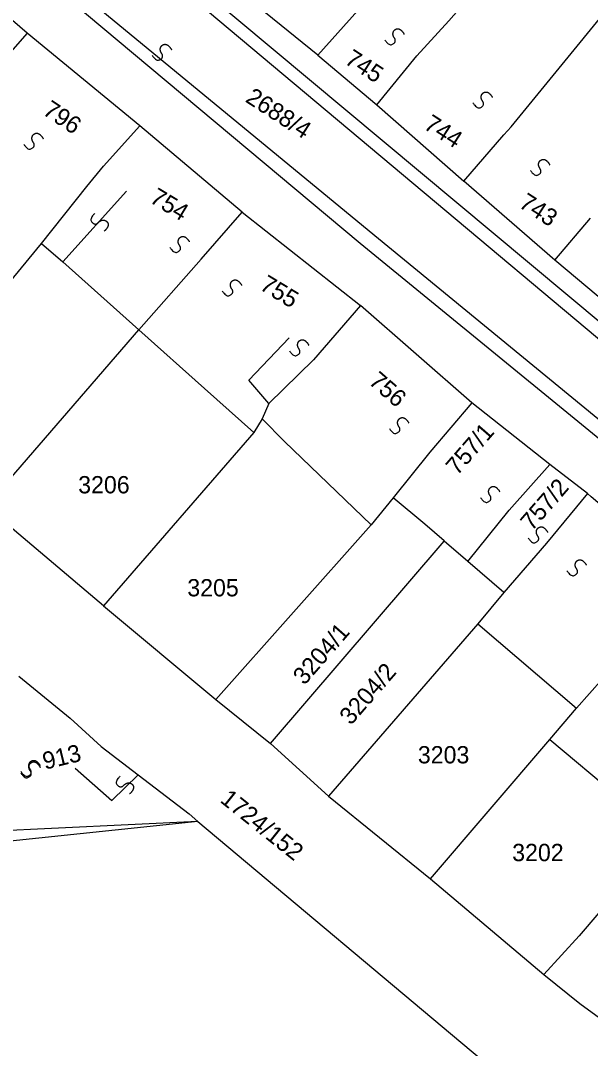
# Model space of a CAD drawing. Extents: x -581999 to -572728, y -1219553 to -1212032.
# Drawn here: x -578520.6 to -578454.7, y -1215566 to -1215447.1 of the extents above; entities that cross this region are included whole.
import ezdxf

# ---------------------------------------------------------------- set-up
doc = ezdxf.new("R2010")
doc.units = 0
for name, color, linetype in [('Vrstva 1', 7, 'Continuous'), ('Vrstva 2', 7, 'Continuous'), ('Vrstva 4', 7, 'Continuous'), ('Vrstva 6', 7, 'Continuous')]:
    doc.layers.add(name, color=color, linetype=linetype)

msp = doc.modelspace()

# ---------------------------------------------------------------- linework, layer by layer
at = {"layer": 'Vrstva 1'}
for p, q in [((-578477.551, -1215502.316), (-578480.099, -1215505.441)), ((-578480.099, -1215505.441), (-578498.028, -1215525.656)), ((-578500.138, -1215539.76), (-578537.866, -1215543.74)), ((-578500.138, -1215539.76), (-578467.315, -1215567.303))]:
    msp.add_line(p, q, dxfattribs=at)
for points in [[(-578471.09, -1215447.169), (-578456.35, -1215430.437)], [(-578519.857, -1215448.603), (-578526.636, -1215442.735), (-578533.826, -1215437.135)], [(-578463.903, -1215459.404), (-578447.102, -1215438.847)], [(-578504.23, -1215439.686), (-578419.077, -1215510.839)], [(-578518.647, -1215441.616), (-578481.363, -1215472.872)], [(-578486.244, -1215451.147), (-578495.73, -1215443.433)], [(-578481.605, -1215445.983), (-578486.244, -1215451.147)], [(-578474.801, -1215451.197), (-578471.09, -1215447.169)], [(-578519.857, -1215448.603), (-578524.032, -1215453.273)], [(-578506.841, -1215459.305), (-578519.857, -1215448.603)], [(-578486.244, -1215451.147), (-578479.439, -1215456.879)], [(-578479.439, -1215456.879), (-578474.801, -1215451.197)], [(-578479.439, -1215456.879), (-578469.365, -1215465.703)], [(-578511.015, -1215463.974), (-578506.841, -1215459.305)], [(-578494.997, -1215469.285), (-578506.841, -1215459.305)], [(-578464.727, -1215460.333), (-578463.903, -1215459.404)], [(-578469.365, -1215465.703), (-578464.727, -1215460.333)], [(-578512.957, -1215466.31), (-578511.015, -1215463.974)], [(-578458.834, -1215474.839), (-578469.365, -1215465.703)], [(-578518.199, -1215472.928), (-578512.957, -1215466.31)], [(-578499.753, -1215474.733), (-578494.997, -1215469.285)], [(-578494.997, -1215469.285), (-578481.325, -1215480.074)], [(-578458.834, -1215474.839), (-578454.712, -1215469.985)], [(-578522.277, -1215477.891), (-578518.199, -1215472.928)], [(-578518.199, -1215472.928), (-578515.719, -1215475.014)], [(-578481.363, -1215472.872), (-578433.992, -1215511.611)], [(-578515.719, -1215475.014), (-578506.936, -1215482.904)], [(-578506.936, -1215482.904), (-578499.753, -1215474.733)], [(-578446.669, -1215485.073), (-578458.834, -1215474.839)], [(-578481.325, -1215480.074), (-578486.751, -1215486.386)], [(-578468.429, -1215491.325), (-578481.325, -1215480.074)], [(-578524.621, -1215503.324), (-578506.936, -1215482.904)], [(-578506.936, -1215482.904), (-578499.341, -1215489.68)], [(-578486.751, -1215486.386), (-578491.903, -1215491.423)], [(-578499.341, -1215489.68), (-578493.633, -1215494.772)], [(-578491.903, -1215491.423), (-578492.681, -1215493.205)], [(-578468.429, -1215491.325), (-578473.281, -1215497.063)], [(-578459.402, -1215498.487), (-578468.429, -1215491.325)], [(-578492.681, -1215493.205), (-578493.633, -1215494.772)], [(-578492.681, -1215493.205), (-578490.117, -1215495.804)], [(-578493.633, -1215494.772), (-578511.025, -1215514.8)], [(-578490.117, -1215495.804), (-578480.099, -1215505.441)], [(-578473.281, -1215497.063), (-578477.551, -1215502.316)], [(-578464.134, -1215503.758), (-578459.402, -1215498.487)], [(-578455.068, -1215501.843), (-578459.402, -1215498.487)], [(-578473.862, -1215505.357), (-578477.551, -1215502.316)], [(-578455.068, -1215501.843), (-578459.8, -1215507.554)], [(-578443.423, -1215511.787), (-578454.656, -1215502.207), (-578455.045, -1215501.815), (-578455.068, -1215501.843)], [(-578511.025, -1215514.8), (-578524.621, -1215503.324)], [(-578468.913, -1215509.672), (-578464.134, -1215503.758)], [(-578471.624, -1215507.325), (-578471.63, -1215507.318), (-578473.862, -1215505.357)], [(-578491.718, -1215530.756), (-578471.624, -1215507.325)], [(-578468.913, -1215509.672), (-578471.624, -1215507.325)], [(-578459.8, -1215507.554), (-578464.749, -1215513.291)], [(-578464.749, -1215513.291), (-578468.913, -1215509.672)], [(-578464.749, -1215513.291), (-578467.757, -1215516.889)], [(-578511.025, -1215514.8), (-578498.028, -1215525.656)], [(-578467.757, -1215516.889), (-578485.029, -1215536.824)], [(-578467.757, -1215516.889), (-578456.328, -1215526.663)], [(-578520.831, -1215522.95), (-578514.896, -1215527.797)], [(-578456.328, -1215526.663), (-578453.319, -1215523.26)], [(-578498.028, -1215525.656), (-578491.718, -1215530.756)], [(-578459.432, -1215530.26), (-578456.328, -1215526.663)], [(-578514.896, -1215527.797), (-578511.286, -1215531.103), (-578507.032, -1215534.367)], [(-578491.718, -1215530.756), (-578485.029, -1215536.824)], [(-578473.211, -1215546.401), (-578459.432, -1215530.26)], [(-578459.432, -1215530.26), (-578451.583, -1215536.838)], [(-578507.032, -1215534.367), (-578501.109, -1215538.878), (-578500.138, -1215539.76), (-578532.369, -1215541.293)], [(-578485.029, -1215536.824), (-578473.211, -1215546.401)], [(-578446.238, -1215541.531), (-578456.037, -1215553.003)], [(-578473.211, -1215546.401), (-578460.112, -1215557.474)], [(-578456.037, -1215553.003), (-578460.112, -1215557.474)], [(-578460.112, -1215557.474), (-578455.94, -1215560.806)], [(-578455.94, -1215560.806), (-578449.558, -1215565.489)]]:
    msp.add_lwpolyline(points, dxfattribs=at)
at = {"layer": 'Vrstva 4'}
for p, q in [((-578514.298, -1215533.592), (-578510.056, -1215537.321)), ((-578510.056, -1215537.321), (-578507.032, -1215534.367))]:
    msp.add_line(p, q, dxfattribs=at)
for points in [[(-578505.224, -1215440.747), (-578421.464, -1215511.032)], [(-578516.36, -1215441.712), (-578479.233, -1215472.341)], [(-578515.719, -1215475.014), (-578508.358, -1215466.857)], [(-578479.233, -1215472.341), (-578312.417, -1215609.28)], [(-578489.562, -1215483.807), (-578494.245, -1215488.722)], [(-578491.903, -1215491.423), (-578494.245, -1215488.722)]]:
    msp.add_lwpolyline(points, dxfattribs=at)
at = {"layer": 'Vrstva 6'}
for points in [[(-578478.511, -1215449.348), (-578478.031, -1215450.055), (-578477.337, -1215449.744), (-578477.26, -1215449.344), (-578477.496, -1215448.999), (-578477.581, -1215448.667), (-578477.499, -1215448.377), (-578477.355, -1215448.197), (-578477.119, -1215448.069), (-578476.754, -1215448.105), (-578476.327, -1215448.544), (-578476.272, -1215448.717)], [(-578505.42, -1215451.141), (-578504.94, -1215451.848), (-578504.246, -1215451.537), (-578504.169, -1215451.137), (-578504.405, -1215450.792), (-578504.49, -1215450.46), (-578504.408, -1215450.17), (-578504.264, -1215449.99), (-578504.028, -1215449.862), (-578503.663, -1215449.898), (-578503.236, -1215450.337), (-578503.181, -1215450.51)], [(-578468.311, -1215456.656), (-578467.831, -1215457.363), (-578467.137, -1215457.052), (-578467.06, -1215456.652), (-578467.296, -1215456.307), (-578467.381, -1215455.975), (-578467.299, -1215455.685), (-578467.155, -1215455.505), (-578466.919, -1215455.377), (-578466.554, -1215455.413), (-578466.127, -1215455.852), (-578466.072, -1215456.025)], [(-578520.263, -1215461.424), (-578519.783, -1215462.131), (-578519.089, -1215461.82), (-578519.012, -1215461.42), (-578519.248, -1215461.075), (-578519.333, -1215460.743), (-578519.251, -1215460.453), (-578519.107, -1215460.273), (-578518.871, -1215460.145), (-578518.506, -1215460.181), (-578518.079, -1215460.62), (-578518.024, -1215460.793)], [(-578461.672, -1215464.451), (-578461.192, -1215465.158), (-578460.498, -1215464.847), (-578460.421, -1215464.447), (-578460.657, -1215464.102), (-578460.742, -1215463.77), (-578460.66, -1215463.48), (-578460.516, -1215463.3), (-578460.28, -1215463.172), (-578459.915, -1215463.208), (-578459.488, -1215463.647), (-578459.433, -1215463.82)], [(-578512.068, -1215469.441), (-578512.655, -1215470.063), (-578512.2, -1215470.672), (-578511.794, -1215470.66), (-578511.508, -1215470.355), (-578511.202, -1215470.201), (-578510.902, -1215470.217), (-578510.695, -1215470.319), (-578510.519, -1215470.522), (-578510.474, -1215470.886), (-578510.809, -1215471.398), (-578510.967, -1215471.49)], [(-578503.348, -1215473.369), (-578502.868, -1215474.076), (-578502.174, -1215473.765), (-578502.097, -1215473.365), (-578502.333, -1215473.02), (-578502.418, -1215472.688), (-578502.336, -1215472.398), (-578502.192, -1215472.218), (-578501.956, -1215472.09), (-578501.591, -1215472.126), (-578501.164, -1215472.565), (-578501.109, -1215472.738)], [(-578497.307, -1215478.389), (-578496.827, -1215479.096), (-578496.133, -1215478.785), (-578496.056, -1215478.385), (-578496.292, -1215478.04), (-578496.377, -1215477.708), (-578496.295, -1215477.418), (-578496.151, -1215477.238), (-578495.915, -1215477.11), (-578495.55, -1215477.146), (-578495.123, -1215477.585), (-578495.068, -1215477.758)], [(-578489.541, -1215485.313), (-578489.061, -1215486.02), (-578488.367, -1215485.709), (-578488.29, -1215485.309), (-578488.526, -1215484.964), (-578488.611, -1215484.632), (-578488.529, -1215484.342), (-578488.385, -1215484.162), (-578488.149, -1215484.034), (-578487.784, -1215484.07), (-578487.357, -1215484.509), (-578487.302, -1215484.682)], [(-578477.977, -1215494.315), (-578477.497, -1215495.022), (-578476.803, -1215494.711), (-578476.726, -1215494.311), (-578476.962, -1215493.966), (-578477.047, -1215493.634), (-578476.965, -1215493.344), (-578476.821, -1215493.164), (-578476.585, -1215493.036), (-578476.22, -1215493.072), (-578475.793, -1215493.511), (-578475.738, -1215493.684)], [(-578467.449, -1215502.278), (-578466.969, -1215502.985), (-578466.275, -1215502.674), (-578466.198, -1215502.274), (-578466.434, -1215501.929), (-578466.519, -1215501.597), (-578466.437, -1215501.307), (-578466.293, -1215501.127), (-578466.057, -1215500.999), (-578465.692, -1215501.035), (-578465.265, -1215501.474), (-578465.21, -1215501.647)], [(-578461.925, -1215506.953), (-578461.445, -1215507.66), (-578460.751, -1215507.349), (-578460.674, -1215506.949), (-578460.91, -1215506.604), (-578460.995, -1215506.272), (-578460.913, -1215505.982), (-578460.769, -1215505.802), (-578460.533, -1215505.674), (-578460.168, -1215505.71), (-578459.741, -1215506.149), (-578459.686, -1215506.322)], [(-578457.438, -1215510.761), (-578456.958, -1215511.468), (-578456.264, -1215511.157), (-578456.187, -1215510.757), (-578456.423, -1215510.412), (-578456.508, -1215510.08), (-578456.426, -1215509.79), (-578456.282, -1215509.61), (-578456.046, -1215509.482), (-578455.681, -1215509.518), (-578455.254, -1215509.957), (-578455.199, -1215510.13)], [(-578520.608, -1215533.959), (-578520.128, -1215534.666), (-578519.434, -1215534.355), (-578519.357, -1215533.955), (-578519.593, -1215533.61), (-578519.678, -1215533.278), (-578519.596, -1215532.988), (-578519.452, -1215532.808), (-578519.216, -1215532.68), (-578518.851, -1215532.716), (-578518.424, -1215533.155), (-578518.369, -1215533.328)], [(-578520.608, -1215534.132), (-578520.128, -1215534.839), (-578519.434, -1215534.528), (-578519.357, -1215534.128), (-578519.593, -1215533.783), (-578519.678, -1215533.451), (-578519.596, -1215533.161), (-578519.452, -1215532.981), (-578519.216, -1215532.853), (-578518.851, -1215532.889), (-578518.424, -1215533.328), (-578518.369, -1215533.501)], [(-578509.134, -1215534.531), (-578509.721, -1215535.153), (-578509.266, -1215535.762), (-578508.86, -1215535.75), (-578508.574, -1215535.445), (-578508.268, -1215535.291), (-578507.968, -1215535.307), (-578507.761, -1215535.409), (-578507.585, -1215535.612), (-578507.54, -1215535.976), (-578507.875, -1215536.488), (-578508.033, -1215536.58)]]:
    msp.add_open_spline(points, degree=2, dxfattribs=at)

# ---------------------------------------------------------------- texts
at = {"layer": 'Vrstva 2'}
for s, rotation, p in [('745', 327.11662, (-578483.269, -1215452.016)), ('2688/4', 327.11662, (-578494.742, -1215456.455)), ('796', 326.30256, (-578518.188, -1215457.893)), ('744', 327.11662, (-578474.128, -1215459.558)), ('754', 328.77499, (-578505.816, -1215468.074)), ('743', 327.11662, (-578463.127, -1215468.628)), ('755', 328.77499, (-578493.096, -1215478.151)), ('756', 319.04972, (-578480.485, -1215489.058)), ('757/1', 48.9575, (-578470.119, -1215499.826)), ('757/2', 48.9575, (-578461.488, -1215506.25)), ('3204/1', 48.9575, (-578487.801, -1215524.084)), ('3204/2', 48.9575, (-578482.419, -1215528.713)), ('913', 13.63187, (-578517.804, -1215533.78)), ('1724/152', 321.3452, (-578497.664, -1215537.44))]:
    msp.add_text(s, height=2, rotation=rotation, dxfattribs=at).set_placement(p)
for s, p in [('3206', (-578513.959, -1215501.811)), ('3205', (-578501.342, -1215513.725)), ('3203', (-578474.679, -1215533.042)), ('3202', (-578463.771, -1215544.347))]:
    msp.add_text(s, height=2, dxfattribs=at).set_placement(p)

doc.saveas('drawing.dxf')
